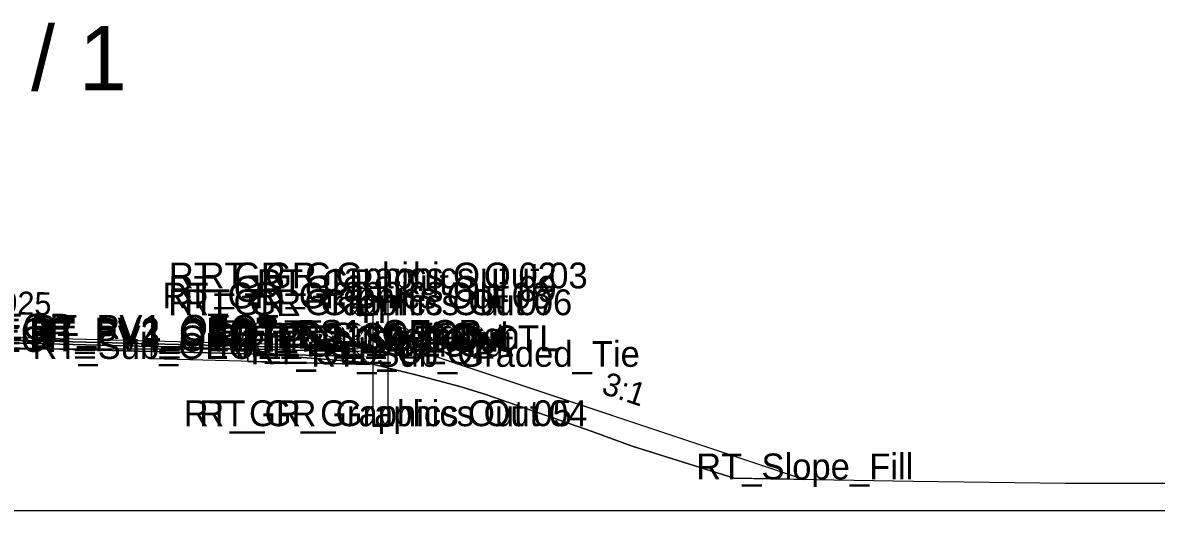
# Model space of a CAD drawing. Extents: x -14026 to 1303, y -10 to 9533.
# Drawn here: x 156.39 to 205.73, y 4000 to 4021.23 of the extents above; entities that cross this region are included whole.
import ezdxf

# ---------------------------------------------------------------- set-up
doc = ezdxf.new("R2010")
doc.units = 0
for name, color, linetype in [('Exist Cross Section Cell', 7, 'Continuous'), ('Exist XS Ground Line', 7, 'Continuous'), ('Prop CMT Guardrail Graphics', 7, 'Continuous'), ('Prop CMT Pvmt Course 1', 7, 'Continuous'), ('Prop CMT Pvmt Course 2', 7, 'Continuous'), ('Prop CMT Pvmt Course 3', 7, 'Continuous'), ('Prop CMT Pvmt Course 4', 7, 'Continuous'), ('Prop CMT Pvmt Surface', 7, 'Continuous'), ('Prop CMT Pvmt Surface Shoulder', 7, 'Continuous'), ('Prop CMT Shld Paved Course 1', 7, 'Continuous'), ('Prop CMT Shld Paved Course 2', 7, 'Continuous'), ('Prop CMT Shld Paved Course 3', 7, 'Continuous'), ('Prop CMT Shld Paved Course 4', 7, 'Continuous'), ('Prop CMT Slope Grass', 7, 'Continuous'), ('Prop CMT Subgrade Earthwork', 7, 'Continuous'), ('Prop XS Earthwork Shape', 7, 'Continuous'), ('Prop XS SE Text', 7, 'Continuous'), ('Prop XS Side Slope Text', 7, 'Continuous'), ('Scratch_Level_0', 7, 'Continuous')]:
    doc.layers.add(name, color=color, linetype=linetype)

msp = doc.modelspace()

# ---------------------------------------------------------------- linework, layer by layer
at = {"layer": 'Exist Cross Section Cell'}
msp.add_line((150, 4000), (300, 4000), dxfattribs=at)
at = {"layer": 'Exist XS Ground Line'}
msp.add_lwpolyline([(154.881, 4007.014), (166.19, 4007.028), (167.862, 4006.717), (171.321, 4006.432), (173.559, 4005.889), (175.417, 4005.394), (176.506, 4005.053), (181.177, 4003.435), (182.922, 4002.792), (187.361, 4001.399), (195.16, 4001.273), (201.765, 4001.182), (211.568, 4001.18)], dxfattribs=at)
at = {"layer": 'Prop CMT Guardrail Graphics'}
for points in [[(172.292, 4009.664), (170.958, 4009.664), (170.687, 4009.372)], [(170.687, 4009.372), (170.958, 4009.081)], [(172.292, 4003.664), (172.292, 4009.664)], [(170.958, 4009.081), (170.687, 4008.789)], [(170.687, 4008.789), (170.958, 4008.497), (171.625, 4008.497)], [(171.625, 4008.497), (171.625, 4003.664)], [(171.625, 4003.664), (172.292, 4003.664)]]:
    msp.add_lwpolyline(points, dxfattribs=at)
at = {"layer": 'Prop CMT Pvmt Course 1'}
for points in [[(150, 4007.682), (162, 4007.382)], [(162, 4007.257), (150, 4007.557)], [(162, 4007.382), (162, 4007.257)]]:
    msp.add_lwpolyline(points, dxfattribs=at)
at = {"layer": 'Prop CMT Pvmt Course 2'}
for points in [[(150, 4007.557), (162, 4007.257)], [(162, 4007.132), (150, 4007.432)], [(162, 4007.257), (162, 4007.132)]]:
    msp.add_lwpolyline(points, dxfattribs=at)
at = {"layer": 'Prop CMT Pvmt Course 3'}
for points in [[(150, 4007.432), (162, 4007.132)], [(162, 4006.922), (150, 4007.222)], [(162, 4007.132), (162, 4006.922)]]:
    msp.add_lwpolyline(points, dxfattribs=at)
at = {"layer": 'Prop CMT Pvmt Course 4'}
for points in [[(150, 4007.222), (162, 4006.922)], [(162, 4006.922), (162, 4006.592)]]:
    msp.add_lwpolyline(points, dxfattribs=at)
at = {"layer": 'Prop CMT Pvmt Surface'}
msp.add_lwpolyline([(150, 4007.682), (162, 4007.382)], dxfattribs=at)
at = {"layer": 'Prop CMT Pvmt Surface Shoulder'}
msp.add_lwpolyline([(162, 4007.382), (170.677, 4007.165)], dxfattribs=at)
at = {"layer": 'Prop CMT Shld Paved Course 1'}
for points in [[(162, 4007.382), (170.677, 4007.165), (170.806, 4007.036)], [(162, 4007.257), (162, 4007.382)], [(170.806, 4007.036), (162, 4007.257)]]:
    msp.add_lwpolyline(points, dxfattribs=at)
at = {"layer": 'Prop CMT Shld Paved Course 2'}
for points in [[(162, 4007.257), (170.806, 4007.036)], [(162, 4007.132), (162, 4007.257)], [(170.934, 4006.908), (162, 4007.132)], [(170.806, 4007.036), (170.806, 4007.036)], [(170.806, 4007.036), (170.934, 4006.908)]]:
    msp.add_lwpolyline(points, dxfattribs=at)
at = {"layer": 'Prop CMT Shld Paved Course 3'}
for points in [[(162, 4007.132), (170.934, 4006.908)], [(162, 4006.922), (162, 4007.132)], [(171.149, 4006.693), (162, 4006.922)], [(170.934, 4006.908), (170.934, 4006.908)], [(170.934, 4006.908), (171.149, 4006.693)]]:
    msp.add_lwpolyline(points, dxfattribs=at)
at = {"layer": 'Prop CMT Shld Paved Course 4'}
for points in [[(162, 4006.922), (171.149, 4006.693), (171.488, 4006.354)], [(162, 4006.592), (162, 4006.922)], [(171.488, 4006.354), (162, 4006.592)]]:
    msp.add_lwpolyline(points, dxfattribs=at)
at = {"layer": 'Prop CMT Slope Grass'}
for points in [[(170.677, 4007.165), (173.678, 4006.925)], [(173.678, 4006.925), (190.421, 4001.349)]]:
    msp.add_lwpolyline(points, dxfattribs=at)
at = {"layer": 'Prop CMT Subgrade Earthwork'}
msp.add_line((166.19, 4007.028), (166.19, 4006.487), dxfattribs=at)
for points in [[(171.488, 4006.354), (172.178, 4007.045), (173.678, 4006.925)], [(173.678, 4006.925), (175.707, 4006.249)], [(166.19, 4006.487), (171.488, 4006.354)], [(175.707, 4006.249), (190.421, 4001.349)]]:
    msp.add_lwpolyline(points, dxfattribs=at)
at = {"layer": 'Prop XS Earthwork Shape'}
msp.add_lwpolyline([(150, 4007.682), (162, 4007.382), (170.677, 4007.165), (173.678, 4006.925), (190.421, 4001.349), (187.361, 4001.399), (182.922, 4002.792), (181.177, 4003.435), (176.506, 4005.053), (175.417, 4005.394), (173.559, 4005.889), (171.321, 4006.432), (167.862, 4006.717), (166.19, 4007.028), (154.881, 4007.014)], dxfattribs=at)
for points in [[(167.862, 4006.717), (171.321, 4006.432), (171.517, 4006.384), (171.488, 4006.354), (166.19, 4006.487), (166.19, 4007.028)], [(175.707, 4006.249), (190.421, 4001.349), (187.361, 4001.399), (182.922, 4002.792), (181.177, 4003.435), (176.506, 4005.053), (175.417, 4005.394), (173.559, 4005.889), (171.517, 4006.384), (172.178, 4007.045), (173.678, 4006.925)]]:
    msp.add_lwpolyline(points, close=True, dxfattribs=at)

# ---------------------------------------------------------------- texts
at = {"layer": 'Exist Cross Section Cell'}
msp.add_text('18+00.00 / 1', height=2.8, dxfattribs=at).set_placement((140, 4018.285))
at = {"layer": 'Prop XS SE Text'}
msp.add_text('0.025', height=1, rotation=358.5679, dxfattribs=at).set_placement((154.291, 4008.575))
at = {"layer": 'Prop XS Side Slope Text'}
msp.add_text('3:1', height=1, rotation=341.5822, dxfattribs=at).set_placement((181.534, 4005.099))
at = {"layer": 'Scratch_Level_0'}
for s, p in [('RT_GR_Graphics Out 02', (162.752, 4009.664)), ('RT_GR_Graphics Out 03', (164.092, 4009.664)), ('RT_GR_Graphics Out 09', (162.743, 4009.081)), ('RT_GR_Out', (166.586, 4009.372)), ('RT_GR_Graphics Out 08', (162.471, 4008.789)), ('RT_GR_Graphics Out 07', (162.724, 4008.497)), ('RT_GR_Graphics Out 06', (163.419, 4008.497)), ('LT_Wedge_PV2_IEEOP', (142.018, 4007.223)), ('LT_Wedge_PV1_IEEOP', (142.094, 4007.432)), ('RT_PV2_OEOT', (156.681, 4007.257)), ('RT_PV3_OEOT', (156.681, 4007.132)), ('RT_PV1_OEOT', (156.757, 4007.382)), ('RT_PS2_Shelf Out', (164.599, 4007.036)), ('RT_PS1_OEOP', (165.491, 4007.165)), ('RT_Sub_Trench', (166.983, 4007.045)), ('LT_Wedge_PV3_IEEOP', (142.018, 4006.89)), ('RT_PV4_OEOT', (156.681, 4006.922)), ('RT_Sub_OEOT', (156.814, 4006.592)), ('RT_PS3_Shelf Out', (164.727, 4006.908)), ('RT_PS4_Shelf Out', (164.943, 4006.693)), ('RT_PS2_OEOP', (165.542, 4007.036)), ('RT_PS3_OEOP', (165.67, 4006.908)), ('RT_PS4_OEOP', (165.886, 4006.693)), ('RT_GS_OS_CTL', (167.999, 4006.925)), ('RT_Sub_OEOP', (166.312, 4006.354)), ('RT_Sub_Graded_Tie', (168.949, 4006.249)), ('RT_GR_Graphics Out 05', (163.401, 4003.664)), ('RT_GR_Graphics Out 04', (164.078, 4003.664)), ('RT_Slope_Fill', (185.701, 4001.349))]:
    msp.add_text(s, height=1.125, dxfattribs=at).set_placement(p)

doc.saveas('drawing.dxf')
